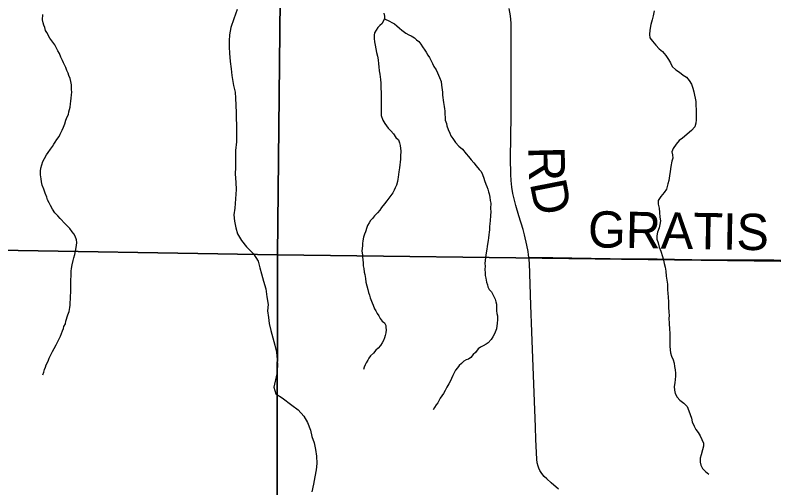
# Model space of a CAD drawing. Extents: x -8.8 to 41.4, y 0 to 34.6.
# Drawn here: x -4.847 to -3.661, y 15.077 to 15.817 of the extents above; entities that cross this region are included whole.
import ezdxf

# ---------------------------------------------------------------- set-up
doc = ezdxf.new("R2010")
doc.units = 0
for name, color, linetype in [('GM_X_Corporation', 7, 'Continuous'), ('GM_X_County_Road', 7, 'Continuous'), ('GM_X_Minor_River', 7, 'Continuous'), ('GM_X_Section_Text', 7, 'Continuous'), ('GM_X_Township_Road', 7, 'Continuous'), ('GM_X_Township_Road_Text', 7, 'Continuous')]:
    doc.layers.add(name, color=color, linetype=linetype)

msp = doc.modelspace()

# ---------------------------------------------------------------- linework, layer by layer
at = {"layer": 'GM_X_Corporation'}
for points in [[(-5.4203, 16.5519), (-4.4254, 16.539), (-4.4369, 15.4422), (-5.4351, 15.4586), (-5.4349, 15.5503)], [(-4.4254, 16.539), (-3.4233, 16.5283), (-3.4436, 15.4293), (-4.4369, 15.4422)], [(-5.4351, 15.4586), (-4.4369, 15.4422), (-4.4383, 14.4395), (-5.4401, 14.4488), (-5.4406, 14.5401)], [(-4.4369, 15.4422), (-3.4436, 15.4293), (-3.4507, 14.4245), (-4.4383, 14.4395)]]:
    msp.add_lwpolyline(points, close=True, dxfattribs=at)
at = {"layer": 'GM_X_County_Road'}
msp.add_lwpolyline([(-3.9977, 15.0755), (-4.0091, 15.0853), (-4.016, 15.0914), (-4.0198, 15.0952), (-4.0238, 15.0998), (-4.0269, 15.1048), (-4.0284, 15.1081), (-4.0296, 15.1116), (-4.0308, 15.1167), (-4.0315, 15.1226), (-4.0332, 15.1532), (-4.0335, 15.1727), (-4.0354, 15.2259), (-4.0391, 15.3215), (-4.0408, 15.3631), (-4.0431, 15.4289), (-4.0439, 15.4382), (-4.0443, 15.4419), (-4.0452, 15.4475), (-4.0471, 15.4573), (-4.0508, 15.4731), (-4.0529, 15.4815), (-4.0594, 15.5029), (-4.0643, 15.5195), (-4.0669, 15.5297), (-4.0688, 15.5382), (-4.0704, 15.548), (-4.0716, 15.5584), (-4.0721, 15.5676), (-4.0724, 15.5931), (-4.0716, 15.6595), (-4.0714, 15.7621), (-4.0714, 15.7901), (-4.0716, 15.8044), (-4.0726, 15.8162), (-4.0745, 15.8274)], dxfattribs=at)
at = {"layer": 'GM_X_Minor_River'}
for points in [[(-4.5, 15.8257), (-4.505, 15.8114), (-4.5099, 15.7975), (-4.5121, 15.7865), (-4.5124, 15.777), (-4.5123, 15.7671), (-4.5118, 15.7576), (-4.511, 15.7447), (-4.5095, 15.7329), (-4.5082, 15.7226), (-4.5056, 15.7069), (-4.5033, 15.6966), (-4.5024, 15.6871), (-4.5015, 15.665), (-4.5014, 15.6555), (-4.5013, 15.6453), (-4.5013, 15.6309), (-4.5013, 15.6187), (-4.5024, 15.6051), (-4.5024, 15.5921), (-4.5028, 15.5785), (-4.5034, 15.5686), (-4.5023, 15.5553), (-4.5018, 15.5443), (-4.5026, 15.5295), (-4.5038, 15.5151), (-4.5052, 15.5045), (-4.5043, 15.4946), (-4.5023, 15.4843), (-4.4996, 15.4747), (-4.4934, 15.4643), (-4.4853, 15.4545), (-4.4746, 15.4436), (-4.4674, 15.432), (-4.4646, 15.4217), (-4.4622, 15.4121), (-4.4588, 15.401), (-4.4553, 15.3891), (-4.4538, 15.3762), (-4.4518, 15.3643), (-4.4525, 15.3545), (-4.4509, 15.3442), (-4.45, 15.3347), (-4.4476, 15.3236), (-4.4442, 15.3121)], [(-4.7929, 15.7813), (-4.7979, 15.7898), (-4.7997, 15.7932), (-4.8007, 15.7978), (-4.8025, 15.8013), (-4.8036, 15.8048), (-4.8042, 15.8097), (-4.804, 15.8181)], [(-4.2708, 15.8201), (-4.2698, 15.8155), (-4.2699, 15.8113), (-4.2715, 15.8076), (-4.2735, 15.8042), (-4.277, 15.8009), (-4.2802, 15.7976), (-4.2829, 15.7935), (-4.2853, 15.7894), (-4.2858, 15.7856), (-4.2856, 15.7806), (-4.2853, 15.7753), (-4.2844, 15.7699), (-4.283, 15.7642), (-4.282, 15.7585), (-4.2807, 15.7527), (-4.2797, 15.747), (-4.2791, 15.7409), (-4.2785, 15.736), (-4.2779, 15.7299), (-4.2769, 15.7249), (-4.2763, 15.7207), (-4.276, 15.7165), (-4.2754, 15.7104), (-4.2752, 15.7055), (-4.2753, 15.702), (-4.275, 15.6971), (-4.2748, 15.6925), (-4.2749, 15.6884), (-4.2747, 15.6834), (-4.275, 15.6709), (-4.2746, 15.6602), (-4.2725, 15.6526), (-4.2692, 15.6475), (-4.2663, 15.644), (-4.2638, 15.6402), (-4.2597, 15.6359), (-4.2557, 15.6312), (-4.252, 15.6258), (-4.2479, 15.6222), (-4.2462, 15.6172), (-4.2452, 15.613), (-4.2445, 15.6085), (-4.2443, 15.6047), (-4.2445, 15.5959), (-4.2446, 15.5917), (-4.2462, 15.5781), (-4.2471, 15.5721), (-4.2481, 15.5637), (-4.2489, 15.5603), (-4.2494, 15.5569), (-4.2511, 15.5509), (-4.2527, 15.5468), (-4.2544, 15.543), (-4.2568, 15.5393), (-4.2599, 15.5348), (-4.2631, 15.5307), (-4.2658, 15.5266), (-4.2694, 15.5218), (-4.2741, 15.5162), (-4.2769, 15.5121), (-4.2808, 15.5076), (-4.2851, 15.5032), (-4.2886, 15.4991), (-4.2914, 15.4958), (-4.2938, 15.4921), (-4.2962, 15.4879), (-4.2974, 15.4846), (-4.2995, 15.4782), (-4.3007, 15.4744), (-4.3024, 15.4695), (-4.3033, 15.4642), (-4.3042, 15.46), (-4.3043, 15.4559), (-4.3047, 15.4525), (-4.3049, 15.4479), (-4.3043, 15.4422), (-4.304, 15.4384), (-4.3037, 15.435), (-4.3031, 15.4292), (-4.3029, 15.4247)], [(-3.848, 15.8237), (-3.8497, 15.8158), (-3.851, 15.8097), (-3.8531, 15.8022), (-3.8545, 15.7935), (-3.8555, 15.7867), (-3.8545, 15.7817), (-3.8508, 15.7763), (-3.8453, 15.77), (-3.8402, 15.7642), (-3.835, 15.7603), (-3.8298, 15.754), (-3.8255, 15.7478), (-3.8226, 15.7424), (-3.8197, 15.7366), (-3.8142, 15.7315), (-3.8082, 15.7276), (-3.8026, 15.7232), (-3.7974, 15.72), (-3.7934, 15.7146), (-3.7898, 15.7092), (-3.7873, 15.703), (-3.7859, 15.6969), (-3.7849, 15.692), (-3.7836, 15.687), (-3.7829, 15.682), (-3.7828, 15.6752), (-3.7825, 15.6698), (-3.7823, 15.6638), (-3.7821, 15.6588), (-3.7822, 15.6535), (-3.7828, 15.6482), (-3.7844, 15.6425), (-3.7895, 15.6366), (-3.8035, 15.6248), (-3.809, 15.6208), (-3.8137, 15.6152), (-3.818, 15.6082), (-3.8201, 15.6033), (-3.8191, 15.5983), (-3.8188, 15.5934), (-3.8201, 15.5885), (-3.8219, 15.5801), (-3.8229, 15.5722), (-3.8242, 15.5654), (-3.8251, 15.5586), (-3.8268, 15.5529), (-3.8289, 15.545), (-3.8321, 15.5398), (-3.8376, 15.5331), (-3.8416, 15.5271), (-3.8418, 15.5214), (-3.8404, 15.5149), (-3.8395, 15.5081), (-3.8389, 15.5008), (-3.8383, 15.4951), (-3.8393, 15.4894), (-3.8401, 15.4845), (-3.8426, 15.4774), (-3.8439, 15.4717), (-3.8437, 15.4668), (-3.8416, 15.4606), (-3.8403, 15.4541), (-3.8378, 15.4476), (-3.835, 15.4392), (-3.8332, 15.4338), (-3.8323, 15.4284), (-3.8309, 15.4227), (-3.8299, 15.4166), (-3.829, 15.4086), (-3.8281, 15.4025), (-3.8271, 15.396), (-3.827, 15.3872), (-3.8267, 15.3819), (-3.8262, 15.3758), (-3.8256, 15.3686), (-3.8255, 15.3602), (-3.8249, 15.3522), (-3.8247, 15.3473), (-3.8248, 15.3423), (-3.8243, 15.3351), (-3.8238, 15.3252), (-3.8236, 15.3199), (-3.8234, 15.3115), (-3.8236, 15.3047), (-3.8234, 15.299), (-3.8228, 15.2936), (-3.8222, 15.2887), (-3.8208, 15.2837), (-3.8183, 15.2776), (-3.8166, 15.2726), (-3.816, 15.2672), (-3.8153, 15.2623), (-3.8147, 15.2569), (-3.8145, 15.252), (-3.815, 15.2471)], [(-4.2699, 15.8113), (-4.2617, 15.8077), (-4.2583, 15.8057), (-4.2542, 15.8037), (-4.2505, 15.8005), (-4.246, 15.7966), (-4.2423, 15.7935), (-4.2364, 15.7891), (-4.2315, 15.7863), (-4.2282, 15.7847), (-4.2229, 15.7815), (-4.2196, 15.7787), (-4.2159, 15.776), (-4.2126, 15.7717), (-4.2101, 15.7675), (-4.2068, 15.7624), (-4.2046, 15.7589), (-4.2017, 15.7547), (-4.1995, 15.7508), (-4.1945, 15.7416), (-4.1923, 15.7366), (-4.1891, 15.7315), (-4.1869, 15.7269), (-4.1851, 15.7234), (-4.1837, 15.7196), (-4.1812, 15.7131), (-4.1803, 15.7073), (-4.179, 15.6967), (-4.1788, 15.6917), (-4.1776, 15.6803), (-4.1763, 15.6742), (-4.1756, 15.6707), (-4.1753, 15.6673), (-4.1751, 15.6612), (-4.1748, 15.6578), (-4.1746, 15.6528), (-4.1729, 15.6475), (-4.1722, 15.6437), (-4.1701, 15.6379), (-4.1676, 15.6325), (-4.1658, 15.6283), (-4.1629, 15.624), (-4.1585, 15.6178), (-4.1534, 15.6123), (-4.1478, 15.6072), (-4.1419, 15.6002), (-4.1383, 15.5959), (-4.1342, 15.5909), (-4.1298, 15.5862), (-4.1265, 15.5812), (-4.1214, 15.5757), (-4.1185, 15.5722), (-4.1163, 15.5676), (-4.1142, 15.5622), (-4.1132, 15.5584), (-4.111, 15.5526), (-4.1096, 15.5488), (-4.1082, 15.5446), (-4.1072, 15.5407), (-4.1062, 15.5373), (-4.1048, 15.5323), (-4.1042, 15.5273), (-4.1035, 15.5231), (-4.1038, 15.5144), (-4.1036, 15.5091), (-4.1041, 15.5034), (-4.1043, 15.4954), (-4.1048, 15.4913), (-4.1053, 15.486), (-4.1055, 15.4814), (-4.106, 15.4776), (-4.1065, 15.4734), (-4.107, 15.4689), (-4.1075, 15.4647), (-4.1084, 15.4587), (-4.1093, 15.4549), (-4.1098, 15.4507), (-4.1107, 15.4454), (-4.1112, 15.4413), (-4.1121, 15.4337), (-4.1127, 15.428), (-4.1124, 15.4246), (-4.1126, 15.4185), (-4.1123, 15.4143), (-4.1121, 15.4098), (-4.1114, 15.4056), (-4.1101, 15.3994), (-4.1087, 15.3952), (-4.108, 15.3918), (-4.1059, 15.3879), (-4.1025, 15.384), (-4.1004, 15.3798), (-4.0982, 15.3759), (-4.0964, 15.3725), (-4.0954, 15.3686), (-4.0947, 15.3648), (-4.0945, 15.3595), (-4.0943, 15.3545), (-4.094, 15.3504), (-4.093, 15.3465), (-4.0928, 15.3408)], [(-4.804, 15.2542), (-4.8024, 15.2583), (-4.8015, 15.2624), (-4.7999, 15.2662), (-4.7986, 15.27), (-4.7958, 15.2756), (-4.7938, 15.2805), (-4.7914, 15.2857), (-4.7886, 15.2906), (-4.7862, 15.2955), (-4.783, 15.3011), (-4.7781, 15.3108), (-4.7765, 15.3149), (-4.7745, 15.3191), (-4.7729, 15.3232), (-4.7716, 15.3266), (-4.7708, 15.33), (-4.7687, 15.3341), (-4.7679, 15.3383), (-4.7646, 15.348), (-4.7629, 15.3533), (-4.7619, 15.3597), (-4.7611, 15.3635), (-4.761, 15.3681), (-4.7605, 15.3722), (-4.76, 15.389), (-4.7602, 15.3958), (-4.7596, 15.4163), (-4.7591, 15.4205), (-4.7582, 15.4265), (-4.7564, 15.4333), (-4.7556, 15.4375), (-4.7539, 15.4427), (-4.753, 15.4477), (-4.7512, 15.4567), (-4.7507, 15.4613), (-4.751, 15.4655), (-4.7531, 15.4712), (-4.7556, 15.4747), (-4.7578, 15.4782), (-4.7619, 15.4832), (-4.7659, 15.4875), (-4.7692, 15.4907), (-4.777, 15.4989), (-4.7803, 15.5031), (-4.7851, 15.5078), (-4.7887, 15.5133), (-4.7919, 15.5194), (-4.7941, 15.5233), (-4.7966, 15.5283), (-4.7976, 15.5325), (-4.8001, 15.5383), (-4.8022, 15.5448), (-4.8047, 15.551), (-4.8061, 15.5563), (-4.8067, 15.5609), (-4.8073, 15.5674), (-4.8075, 15.5731), (-4.807, 15.5776), (-4.8057, 15.5829), (-4.804, 15.5882), (-4.8012, 15.593), (-4.7984, 15.5983), (-4.7957, 15.6024), (-4.7917, 15.6072), (-4.7889, 15.6117), (-4.7866, 15.615), (-4.7846, 15.6184), (-4.7818, 15.6225), (-4.7786, 15.627), (-4.7766, 15.6307), (-4.7738, 15.6371), (-4.7718, 15.6416), (-4.7693, 15.6472), (-4.7677, 15.6525), (-4.7656, 15.6578), (-4.764, 15.6615), (-4.7631, 15.6657), (-4.7614, 15.6732), (-4.7605, 15.6781), (-4.76, 15.6823), (-4.7595, 15.6872), (-4.7593, 15.6925), (-4.7588, 15.6967), (-4.7591, 15.7005), (-4.759, 15.7043), (-4.7593, 15.7081), (-4.7603, 15.7135), (-4.7613, 15.7177), (-4.763, 15.7227), (-4.7645, 15.7261), (-4.7662, 15.7307), (-4.768, 15.735), (-4.7716, 15.7427), (-4.7734, 15.7461), (-4.7755, 15.7511), (-4.778, 15.7569), (-4.7805, 15.7615), (-4.783, 15.7666), (-4.7852, 15.7708), (-4.7929, 15.7813)], [(-4.3029, 15.4247), (-4.3022, 15.4209), (-4.3016, 15.4151), (-4.3006, 15.4113), (-4.2996, 15.4048), (-4.2987, 15.3991), (-4.2973, 15.3937), (-4.2956, 15.388), (-4.2946, 15.383), (-4.2932, 15.3792), (-4.2918, 15.3746), (-4.289, 15.3669), (-4.2872, 15.3634), (-4.2851, 15.3577), (-4.2833, 15.3542), (-4.2811, 15.35), (-4.2785, 15.3465), (-4.2764, 15.3426), (-4.2731, 15.3383), (-4.2694, 15.3356), (-4.2676, 15.3317), (-4.2673, 15.3283), (-4.267, 15.3245), (-4.2675, 15.3199), (-4.2684, 15.3158), (-4.2697, 15.312), (-4.2713, 15.3079), (-4.2733, 15.3045), (-4.2761, 15.3004), (-4.2796, 15.296), (-4.2831, 15.293), (-4.287, 15.2882), (-4.2913, 15.2841), (-4.2941, 15.2804), (-4.2957, 15.277), (-4.2981, 15.2733), (-4.3001, 15.2699), (-4.3013, 15.2665), (-4.3026, 15.2624)], [(-4.0928, 15.3408), (-4.0933, 15.3348), (-4.0942, 15.331), (-4.0947, 15.3264), (-4.0964, 15.3212), (-4.098, 15.3174), (-4.1004, 15.3137), (-4.1028, 15.3096), (-4.1075, 15.3044), (-4.1109, 15.3022), (-4.1152, 15.2997), (-4.1194, 15.2975), (-4.1233, 15.2949), (-4.1276, 15.2894), (-4.1308, 15.286), (-4.1347, 15.2816), (-4.1385, 15.279), (-4.142, 15.278), (-4.1458, 15.2758), (-4.149, 15.2721), (-4.1529, 15.2688), (-4.1553, 15.2651), (-4.1584, 15.2617), (-4.16, 15.2584), (-4.1628, 15.2531), (-4.1648, 15.2486), (-4.1664, 15.2449), (-4.1689, 15.2404), (-4.172, 15.2348), (-4.1748, 15.2299), (-4.1773, 15.225), (-4.18, 15.2213), (-4.1824, 15.218), (-4.1864, 15.2105), (-4.1888, 15.2071), (-4.1912, 15.203), (-4.1935, 15.1997)], [(-4.4442, 15.3121), (-4.4411, 15.3006), (-4.4387, 15.2899), (-4.4375, 15.2785), (-4.4367, 15.2682), (-4.4381, 15.2561), (-4.4425, 15.2349), (-4.4394, 15.2246), (-4.4297, 15.2182), (-4.4145, 15.2068), (-4.4048, 15.1993), (-4.396, 15.1896), (-4.3902, 15.1795), (-4.3856, 15.1676), (-4.3832, 15.158), (-4.3797, 15.1477), (-4.3777, 15.1374), (-4.3761, 15.1271), (-4.3753, 15.1157), (-4.3767, 15.1054), (-4.3785, 15.0949), (-4.3807, 15.0832), (-4.3834, 15.0711)], [(-3.815, 15.2471), (-3.8155, 15.2418), (-3.8165, 15.2361), (-3.8162, 15.2304), (-3.8153, 15.225), (-3.812, 15.2196), (-3.8076, 15.2146), (-3.8016, 15.2102), (-3.7965, 15.2047), (-3.7936, 15.1982), (-3.7894, 15.1867), (-3.7884, 15.181), (-3.7856, 15.174), (-3.7827, 15.169), (-3.7794, 15.164), (-3.7762, 15.1586), (-3.7733, 15.1532), (-3.7708, 15.1474), (-3.7709, 15.1425), (-3.7726, 15.1372), (-3.7747, 15.1293), (-3.776, 15.124), (-3.7762, 15.1179), (-3.7748, 15.1129), (-3.7723, 15.1079), (-3.7675, 15.1028), (-3.7623, 15.0989)]]:
    msp.add_lwpolyline(points, dxfattribs=at)
at = {"layer": 'GM_X_Township_Road'}
msp.add_lwpolyline([(-4.0439, 15.4382), (-4.0066, 15.4379), (-3.9166, 15.4363), (-3.8434, 15.4356), (-3.7621, 15.4344), (-3.7186, 15.4342), (-3.6609, 15.4342), (-3.5814, 15.4335), (-3.4286, 15.4315), (-3.343, 15.43), (-3.289, 15.429), (-3.2822, 15.4286), (-3.2763, 15.4283)], dxfattribs=at)

# ---------------------------------------------------------------- texts
at = {"layer": 'GM_X_Section_Text'}
msp.add_text('GRATIS', height=0.05682, rotation=359.0485, dxfattribs=at).set_placement((-3.9518, 15.4538))
at = {"layer": 'GM_X_Township_Road_Text'}
for s, rotation, p in [('R', 271.4111, (-4.0449, 15.6111)), ('D', 281.124, (-4.0426, 15.5542))]:
    msp.add_text(s, height=0.0568, rotation=rotation, dxfattribs=at).set_placement(p)

doc.saveas('drawing.dxf')
